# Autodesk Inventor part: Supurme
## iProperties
Shininess: 64.0
Length Units: 11269
Angle Units: 11279
Time Units: 11290
Mass Units: 11283
Length Display Precision: 3
Angle Display Precision: 2
Compacted: True
Part Number: Supurme
Document SubType Name: Modeling
Created: 2004-03
Designer: Administrator
Manufacturer: Standard
Standards Organization: Custom
Density: 1 g/cm^3
Density: 0.0
Volumn: 0.0
Area: 0.0
PropertySet Name: Model Information
Control State: 0
Master: False
Checked Out: False
Author: Administrator
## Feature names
1. Extrusion1
2. Extrusion2
3. Fillet1
4. Shell1
5. Extrusion3
6. Extrusion4
7. Extrusion5
8. Hole1
9. Fillet2
10. Fillet3
11. Hole2
12. Circular Pattern1
13. Fillet4
